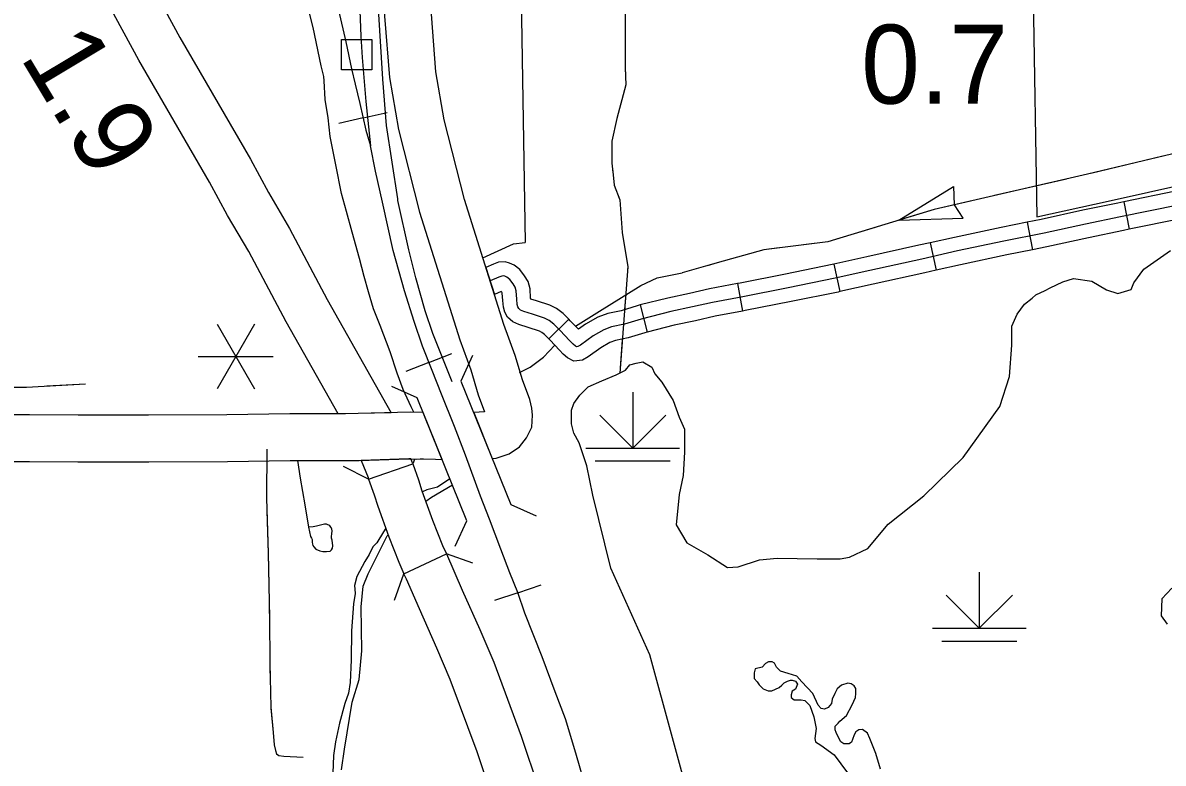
# Model space of a CAD drawing. Extents: x -117616 to 64730, y 54117 to 789866.
# Drawn here: x 63045.9 to 63167.8, y 54498.2 to 54577.4 of the extents above; entities that cross this region are included whole.
import ezdxf

# ---------------------------------------------------------------- set-up
doc = ezdxf.new("R2010")
doc.units = 0
for name, color, linetype in [('10', 7, 'Continuous'), ('32', 7, 'Continuous'), ('33', 7, 'Continuous'), ('34', 7, 'Continuous'), ('35', 7, 'Continuous'), ('37', 7, 'Continuous'), ('40', 7, 'Continuous'), ('43', 7, 'Continuous'), ('44', 7, 'Continuous'), ('47', 7, 'Continuous'), ('48', 7, 'Continuous'), ('6', 7, 'Continuous'), ('7', 7, 'Continuous')]:
    doc.layers.add(name, color=color, linetype=linetype)

msp = doc.modelspace()

# ---------------------------------------------------------------- linework, layer by layer
at = {"layer": '10'}
for p, q in [((63082.88, 54528.56), (63087.6, 54530.2)), ((63086.66, 54518.43), (63091.21, 54520.55)), ((63091.21, 54520.55), (63092.88, 54516.67)), ((63086.94, 54517.83), (63086.66, 54518.43)), ((63088.31, 54514.66), (63086.94, 54517.83)), ((63092.88, 54516.67), (63094.77, 54512.46)), ((63090.19, 54510.46), (63088.31, 54514.66)), ((63094.77, 54512.46), (63096.26, 54508.96)), ((63091.61, 54507.11), (63090.19, 54510.46)), ((63096.26, 54508.96), (63099.21, 54501.06)), ((63094.49, 54499.39), (63091.61, 54507.11)), ((63099.21, 54501.06), (63103.79, 54487.31)), ((63099, 54485.86), (63094.49, 54499.39))]:
    msp.add_line(p, q, dxfattribs=at)
for points in [[(63084.67, 54595.12), (63084.59, 54587.99), (63084.59, 54578.08), (63085.1, 54571.51), (63086.07, 54565.95), (63088.32, 54557.09), (63092.62, 54543.45), (63093.82, 54540.22), (63094.58, 54537.58), (63095.29, 54535.73), (63094.12, 54535.66)], [(63094.12, 54535.66), (63096.09, 54530.77), (63096.52, 54530.8), (63097.91, 54531.26), (63099, 54531.99), (63099.75, 54532.95), (63100.32, 54534.09), (63100.39, 54535.4), (63100.33, 54536.15), (63100.12, 54537.08), (63099.33, 54539.16), (63098.57, 54541.78), (63097.35, 54545.07), (63093.13, 54558.46), (63090.96, 54566.99), (63090.07, 54572.13), (63089.59, 54578.27), (63089.59, 54587.96), (63089.67, 54595.06)], [(63056.63, 54586.99), (63062.68, 54575.79), (63070.24, 54562.76), (63072.17, 54559.22), (63074.43, 54555.34), (63078.46, 54547.76), (63085.31, 54535.65), (63081.78, 54535.55), (63080.42, 54535.54), (63079.63, 54535.54)], [(63079.63, 54535.54), (63074.07, 54545.36), (63070.06, 54552.91), (63067.81, 54556.76), (63065.88, 54560.31), (63058.32, 54573.35), (63052.3, 54584.49)], [(63075.09, 54535.53), (63074.47, 54535.53), (63067.73, 54535.44), (63059.36, 54535.38), (63051.82, 54535.4), (63046.63, 54535.44), (63040.96, 54535.42), (63036.3, 54535.29), (63026.16, 54534.93), (63019.91, 54534.68), (63012.1, 54534.36), (63007.3, 54534.19), (63003.53, 54534.02), (62999.39, 54533.9), (62993.74, 54533.66), (62985.86, 54533.37), (62981.09, 54533.17), (62975.36, 54532.97), (62969.85, 54532.83), (62965.22, 54532.63), (62962.67, 54532.55), (62960.47, 54532.44), (62958.49, 54532.34), (62956.86, 54532.26)], [(63080.42, 54535.54), (63075.09, 54535.53)], [(63087.35, 54535.71), (63081.78, 54535.55), (63080.42, 54535.54)], [(63090.76, 54530.63), (63088.72, 54535.66), (63087.35, 54535.71)], [(62957.03, 54527.26), (62958.75, 54527.35), (62960.72, 54527.45), (62962.86, 54527.55), (62965.41, 54527.63), (62970.02, 54527.84), (62975.51, 54527.97), (62981.28, 54528.18), (62986.06, 54528.38), (62993.94, 54528.67), (62999.57, 54528.9), (63003.72, 54529.02), (63007.5, 54529.2), (63012.29, 54529.36), (63020.11, 54529.69), (63026.35, 54529.93), (63036.46, 54530.29), (63041.04, 54530.42), (63046.62, 54530.44), (63051.79, 54530.4), (63059.37, 54530.38), (63067.78, 54530.44), (63074.51, 54530.53), (63075.1, 54530.53)], [(63075.1, 54530.53), (63080.43, 54530.54)], [(63080.43, 54530.54), (63081.87, 54530.55), (63087.19, 54530.72)], [(63087.6, 54530.2), (63087.51, 54530.48), (63087.41, 54530.71), (63087.19, 54530.72), (63082.08, 54530.55)], [(63082.08, 54530.55), (63082.82, 54528.73), (63082.88, 54528.56)], [(63087.19, 54530.72), (63087.96, 54530.7), (63088.38, 54530.72), (63088.7, 54530.73), (63088.74, 54530.73), (63090.02, 54530.68)], [(63087.6, 54530.2), (63088.2, 54528.46), (63088.58, 54527.31), (63089.73, 54524.14), (63090.77, 54521.46), (63091.21, 54520.55)], [(63090.02, 54530.68), (63090.76, 54530.63)], [(63082.88, 54528.56), (63083.46, 54526.86), (63083.86, 54525.67), (63085.05, 54522.38), (63086.11, 54519.65), (63086.66, 54518.43)]]:
    msp.add_lwpolyline(points, dxfattribs=at)
at = {"layer": '32'}
for p, q in [((63163.62, 54558.21), (63164.22, 54555.27)), ((63153.29, 54556.03), (63153.88, 54553.09)), ((63142.93, 54553.83), (63143.58, 54550.9)), ((63095.43, 54551.18), (63096.33, 54548.3)), ((63132.62, 54551.53), (63133.28, 54548.6)), ((63122.32, 54549.47), (63122.87, 54546.52)), ((63111.92, 54547.18), (63112.65, 54544.27)), ((63104.3, 54545.65), (63102.16, 54543.55))]:
    msp.add_line(p, q, dxfattribs=at)
for points in [[(63174.22, 54559.99), (63174.01, 54560.03), (63173.5, 54560.05), (63172.99, 54560.03), (63172.34, 54559.95), (63171.71, 54559.83), (63170.9, 54559.65), (63169.15, 54559.34), (63163.62, 54558.21)], [(63163.62, 54558.21), (63162.98, 54558.08), (63159.24, 54557.3), (63154.81, 54556.33), (63153.29, 54556.03)], [(63169.43, 54557.86), (63163.28, 54556.61), (63159.55, 54555.83), (63155.12, 54554.86), (63150.82, 54554.01), (63145.84, 54552.95), (63142.04, 54552.09), (63136.49, 54550.86), (63132.78, 54550.03), (63127.76, 54549.01), (63122.88, 54548.04), (63119.65, 54547.44), (63117.51, 54546.96), (63115.21, 54546.46), (63112.02, 54545.66), (63110.25, 54545.11), (63108.87, 54544.82), (63108.02, 54544.51), (63106.88, 54543.86), (63105.53, 54542.89), (63105.25, 54542.72), (63105.1, 54542.71), (63105, 54542.76), (63104.75, 54542.99), (63104.38, 54543.37), (63103.37, 54544.46), (63102.7, 54545.14), (63102.2, 54545.52), (63101.7, 54545.76), (63100.39, 54546.19), (63099.47, 54546.48), (63099.14, 54546.63), (63098.94, 54546.81), (63098.84, 54546.99), (63098.77, 54547.23), (63098.72, 54547.78), (63098.65, 54548.68), (63098.55, 54549.09), (63098.34, 54549.43), (63097.97, 54549.91), (63097.67, 54550.14), (63097.44, 54550.24), (63097.32, 54550.28), (63097.12, 54550.26), (63096.82, 54550.14), (63095.88, 54549.74)], [(63173.89, 54556.99), (63173.8, 54557.02), (63173.68, 54557.04), (63173.49, 54557.05), (63173.24, 54557.04), (63172.79, 54556.98), (63172.31, 54556.89), (63171.49, 54556.71), (63169.71, 54556.39), (63164.22, 54555.27)], [(63153.29, 54556.03), (63150.52, 54555.48), (63145.52, 54554.41), (63142.93, 54553.83)], [(63164.22, 54555.27), (63163.59, 54555.14), (63159.86, 54554.36), (63155.42, 54553.39), (63153.88, 54553.09)], [(63142.93, 54553.83), (63141.71, 54553.56), (63136.16, 54552.32), (63132.62, 54551.53)], [(63153.88, 54553.09), (63151.12, 54552.54), (63146.16, 54551.48), (63143.58, 54550.9)], [(63104.3, 54545.65), (63103.7, 54546.27), (63102.98, 54546.81), (63102.26, 54547.15), (63100.84, 54547.62), (63100.22, 54547.81), (63100.21, 54547.9), (63100.14, 54548.91), (63099.95, 54549.69), (63099.56, 54550.29), (63099.05, 54550.97), (63098.44, 54551.45), (63097.94, 54551.66), (63097.47, 54551.79), (63096.78, 54551.74), (63096.25, 54551.53), (63095.43, 54551.18)], [(63132.62, 54551.53), (63132.46, 54551.49), (63127.47, 54550.48), (63122.6, 54549.52), (63122.32, 54549.47)], [(63143.58, 54550.9), (63142.37, 54550.63), (63136.82, 54549.4), (63133.28, 54548.6)], [(63122.32, 54549.47), (63119.34, 54548.91), (63117.19, 54548.42), (63114.87, 54547.92), (63111.92, 54547.18)], [(63102.16, 54543.55), (63101.7, 54544.02), (63101.42, 54544.23), (63101.15, 54544.36), (63099.93, 54544.76), (63098.94, 54545.07), (63098.3, 54545.36), (63097.74, 54545.87), (63097.44, 54546.42), (63097.29, 54546.95), (63097.22, 54547.65), (63097.17, 54548.44), (63097.15, 54548.49), (63097.11, 54548.56), (63097.07, 54548.62), (63096.33, 54548.3)], [(63096.47, 54548.36), (63096.47, 54548.36)], [(63133.28, 54548.6), (63133.09, 54548.56), (63128.05, 54547.54), (63123.16, 54546.57), (63122.87, 54546.52)], [(63111.92, 54547.18), (63111.61, 54547.1), (63109.87, 54546.56), (63108.45, 54546.27), (63107.38, 54545.87), (63106.07, 54545.12), (63105.31, 54544.58), (63104.45, 54545.49), (63104.3, 54545.65)], [(63122.87, 54546.52), (63119.95, 54545.97), (63117.84, 54545.49), (63115.56, 54545), (63112.65, 54544.27)], [(63112.65, 54544.27), (63112.42, 54544.21), (63110.62, 54543.65), (63109.28, 54543.38), (63108.66, 54543.15), (63107.7, 54542.59), (63106.35, 54541.63), (63105.74, 54541.27), (63104.83, 54541.17), (63104.14, 54541.51), (63103.7, 54541.92), (63103.29, 54542.34), (63102.28, 54543.42), (63102.16, 54543.55)]]:
    msp.add_lwpolyline(points, dxfattribs=at)
at = {"layer": '33'}
msp.add_lwpolyline([(63077.81, 54572.76), (63076.95, 54576.84), (63076.26, 54579.54), (63075.57, 54582.7), (63074.9, 54585.84), (63074.01, 54589.67), (63073.35, 54592.61), (63072.7, 54595.11), (63072.21, 54596.89), (63072.01, 54597.46), (63071.81, 54597.95), (63071.72, 54598.1)], dxfattribs=at)
at = {"layer": '34'}
for points in [[(63087.73, 54535.7), (63087.44, 54536.27), (63086.59, 54538.13), (63085.95, 54539.89), (63085.19, 54542.16), (63084.11, 54544.98), (63083.39, 54546.78), (63082.88, 54548.59), (63082.39, 54550.22), (63081.92, 54552.15), (63081.11, 54554.97), (63080.5, 54557.19), (63079.97, 54559.1), (63079.37, 54562.18), (63078.76, 54565.21), (63078.55, 54567.2), (63078.23, 54569.17), (63078.14, 54571.16), (63078.08, 54571.61), (63077.81, 54572.76)], [(63075.27, 54530.53), (63075.57, 54528.65), (63076.05, 54525.81), (63076.46, 54523.41)], [(63076.46, 54523.41), (63076.56, 54522.91), (63076.68, 54522.41), (63076.76, 54522.24), (63076.83, 54522.1), (63076.85, 54521.96), (63076.86, 54521.8), (63076.88, 54521.58), (63076.92, 54521.45), (63077.02, 54521.29), (63077.24, 54521.05), (63077.66, 54520.86), (63077.97, 54520.8), (63078.37, 54520.8), (63078.76, 54520.85), (63078.91, 54520.98), (63079.01, 54521.15), (63079.05, 54521.42), (63079, 54522.01), (63078.92, 54522.24), (63078.92, 54522.41), (63078.95, 54522.71), (63078.97, 54523.03), (63078.95, 54523.18), (63078.86, 54523.37), (63078.72, 54523.55), (63078.62, 54523.63), (63078.52, 54523.67), (63078.37, 54523.72), (63078.16, 54523.73), (63077.87, 54523.67), (63077.32, 54523.51), (63076.96, 54523.44), (63076.46, 54523.41)]]:
    msp.add_lwpolyline(points, dxfattribs=at)
at = {"layer": '35'}
for points in [[(63104.99, 54544.92), (63107.57, 54546.53), (63111.98, 54549.26), (63113.73, 54550.08), (63116.4, 54550.6)], [(63099.02, 54539.96), (63100.14, 54540.54), (63101.58, 54541.6), (63102.8, 54542.87)], [(63090.24, 54527.69), (63089.1, 54527.39), (63088.63, 54527.18)], [(63088.99, 54526.19), (63089.62, 54526.62), (63091.85, 54527.93)], [(63091.58, 54528.59), (63090.24, 54527.69)], [(63084.72, 54523.3), (63084.47, 54522.92), (63083.76, 54521.73), (63083.32, 54521.3), (63082.94, 54520.49), (63082.48, 54519.74), (63081.61, 54518.13), (63081.38, 54517.17), (63081.4, 54516.78), (63081.45, 54516.3), (63081.26, 54515.22), (63081.06, 54512.31), (63081.01, 54509.21), (63080.92, 54506.78), (63080.74, 54505.66), (63080.35, 54504.56), (63079.77, 54502.45), (63079.34, 54500.46), (63079.13, 54498.99), (63079.04, 54497.11)], [(63082.84, 54518.43), (63084.08, 54520.93), (63084.88, 54522.49), (63084.97, 54522.6)], [(63079.97, 54497.44), (63080.3, 54499.65), (63081.11, 54504.7), (63081.87, 54507.11), (63082.15, 54510.18), (63082.1, 54514.87), (63082.31, 54517.11), (63082.84, 54518.43)], [(63168.78, 54516.88), (63167.71, 54515.73), (63167.63, 54513.93), (63168.28, 54513.05)], [(63137.62, 54497.52), (63137.12, 54499.2), (63136.49, 54500.79), (63136.24, 54501.38), (63135.7, 54501.76), (63135.3, 54501.72), (63134.97, 54501.5), (63134.82, 54501.21), (63134.63, 54500.69), (63134.52, 54500.4), (63134.27, 54500.25), (63133.94, 54500.25), (63133.68, 54500.25), (63133.38, 54500.43), (63133.13, 54500.91), (63132.87, 54501.43), (63132.76, 54501.72), (63132.76, 54502.13), (63133.09, 54502.46), (63133.27, 54502.64), (63133.97, 54503.27), (63134.6, 54504.41), (63134.93, 54505.19), (63134.97, 54505.63), (63134.97, 54506.14), (63134.82, 54506.44), (63134.49, 54506.66), (63134.12, 54506.73), (63133.46, 54506.51), (63132.98, 54506.11), (63132.72, 54505.63), (63132.46, 54505), (63132.39, 54504.56), (63132.02, 54504.12), (63131.62, 54503.93), (63131.29, 54504.01), (63130.95, 54504.38), (63130.4, 54505.63), (63129.19, 54506.88), (63128.67, 54507.47), (63127.75, 54507.76), (63126.94, 54507.99), (63126.5, 54508.43), (63126.28, 54508.87), (63126.02, 54509.02), (63125.65, 54509.02), (63125.32, 54508.83), (63124.96, 54508.43), (63124.22, 54508.24), (63124.11, 54507.84), (63124.11, 54507.54), (63124.11, 54507.21), (63124.44, 54506.88), (63124.66, 54506.55), (63124.81, 54506.36), (63125.07, 54506.11), (63125.62, 54505.89), (63125.99, 54505.89), (63126.8, 54506.25), (63127.05, 54506.51), (63127.31, 54506.77), (63127.68, 54506.95), (63128.01, 54507.03), (63128.19, 54507.03), (63128.53, 54506.92), (63128.75, 54506.62), (63128.67, 54506.44), (63128.53, 54506.07), (63128.16, 54505.85), (63128.05, 54505.48), (63128.08, 54505.19), (63128.38, 54504.93), (63129.15, 54504.93), (63129.52, 54504.85), (63130.07, 54504.34), (63130.48, 54503.12)], [(63130.48, 54503.12), (63130.73, 54501.87), (63130.59, 54500.8), (63130.66, 54500.43), (63131.25, 54500.1), (63132.68, 54499.07), (63134.08, 54497.12)]]:
    msp.add_lwpolyline(points, dxfattribs=at)
at = {"layer": '37'}
for points in [[(63093.99, 54541.76), (63092.76, 54539.02)], [(63088.08, 54537.24), (63085.35, 54538.47)], [(63082.88, 54528.56), (63080.18, 54529.88)], [(63087.8, 54530.63), (63087.6, 54530.2)], [(63098.08, 54525.85), (63100.81, 54524.61)], [(63092.15, 54521.37), (63093.39, 54524.1)], [(63091.18, 54520.58), (63094, 54519.58)], [(63085.66, 54515.61), (63086.66, 54518.43)]]:
    msp.add_lwpolyline(points, dxfattribs=at)
at = {"layer": '40'}
for p, q in [((63082.29, 54567.18), (63084.86, 54567.76)), ((63082.29, 54567.18), (63079.71, 54566.6)), ((63089.33, 54541.02), (63086.87, 54540.07)), ((63089.33, 54541.02), (63091.79, 54541.98)), ((63092.76, 54539.02), (63098.08, 54525.85)), ((63098.85, 54516.4), (63101.35, 54517.24)), ((63098.85, 54516.4), (63096.34, 54515.56))]:
    msp.add_line(p, q, dxfattribs=at)
for points in [[(63070.77, 54618.7), (63071.46, 54616), (63072.4, 54611.53), (63073.22, 54608.04), (63074.22, 54603.33), (63075.12, 54599.36), (63075.67, 54596.47), (63076.72, 54591.57), (63077.85, 54586.72), (63078.84, 54582.33), (63079.65, 54578.7), (63080.43, 54575.33), (63081.05, 54572.42), (63081.45, 54570.81), (63081.94, 54568.73), (63082.59, 54565.88), (63083.07, 54564.21)], [(63075.12, 54599.36), (63075.67, 54596.47), (63076.72, 54591.57), (63077.85, 54586.72), (63078.84, 54582.33), (63079.65, 54578.7), (63080.43, 54575.33), (63081.05, 54572.42), (63081.45, 54570.81), (63081.94, 54568.73), (63082.59, 54565.88), (63083.07, 54564.21)], [(63082.84, 54597.41), (63082.63, 54595.15), (63082.37, 54591.4), (63081.85, 54585.98), (63081.8, 54584.31), (63081.9, 54579.57), (63082.06, 54575.92), (63082.21, 54573.63), (63082.58, 54568.93), (63083.07, 54564.21)], [(63087.74, 54545.41), (63086.71, 54548.69), (63085.52, 54553), (63084.36, 54558.17), (63083.63, 54561.49), (63083.07, 54564.21)], [(63092.08, 54534.18), (63090.69, 54537.65), (63089.66, 54540.17), (63088.65, 54542.78), (63087.74, 54545.41), (63086.71, 54548.69), (63085.52, 54553), (63084.36, 54558.17), (63083.63, 54561.49), (63083.07, 54564.21)], [(63106.35, 54494.66), (63105.05, 54499.25), (63103.95, 54502.9), (63102.84, 54505.81), (63101.43, 54509.54), (63099.58, 54514.21), (63098.84, 54516.43), (63097.98, 54518.53), (63097.01, 54521.07), (63095.8, 54524.25), (63094.83, 54526.72), (63093.23, 54531.11), (63092.08, 54534.18), (63090.69, 54537.65), (63089.66, 54540.17), (63088.65, 54542.78), (63087.74, 54545.41)], [(63093.39, 54524.1), (63088.08, 54537.24)], [(63106.35, 54494.66), (63105.05, 54499.25), (63103.95, 54502.9), (63102.84, 54505.81), (63101.43, 54509.54), (63099.58, 54514.21), (63098.84, 54516.43), (63097.98, 54518.53), (63097.01, 54521.07), (63095.8, 54524.25), (63094.83, 54526.72), (63093.23, 54531.11), (63092.08, 54534.18)]]:
    msp.add_lwpolyline(points, dxfattribs=at)
msp.add_lwpolyline([(63079.97, 54575.58), (63083.24, 54575.58), (63083.24, 54572.31), (63079.97, 54572.31)], close=True, dxfattribs=at)
at = {"layer": '43'}
for p, q in [((63139.59, 54556.24), (63145.42, 54559.86)), ((63145.42, 54559.86), (63145.51, 54557.89)), ((63146.45, 54556.46), (63145.52, 54557.87)), ((63139.59, 54556.24), (63146.45, 54556.46))]:
    msp.add_line(p, q, dxfattribs=at)
for points in [[(63110.67, 54579.58), (63110.33, 54578.56), (63110.33, 54575.19), (63110.33, 54572.53), (63110.35, 54571.71)], [(63110.33, 54578.56), (63110.33, 54575.19), (63110.33, 54572.53), (63110.37, 54570.72), (63109.41, 54567.13), (63108.89, 54564.71), (63108.89, 54562.34), (63109.02, 54561.1), (63109.15, 54559.98), (63109.74, 54558.41), (63110, 54554.93), (63110.59, 54551.26), (63110.33, 54547.52), (63109.73, 54539.87)], [(63207.19, 54577.49), (63207.38, 54574.68), (63206.93, 54572.57), (63206.19, 54571.14), (63205.5, 54570.37), (63204.77, 54569.96), (63203.88, 54569.6), (63202.49, 54569.03), (63201.27, 54568.74), (63198.79, 54568.46), (63191.27, 54568.36), (63186.06, 54568.04), (63173.98, 54564.57), (63159.77, 54561.17), (63143.35, 54557.38), (63131.99, 54553.94), (63125.15, 54553.07), (63120.16, 54551.68), (63116.4, 54550.6)], [(63109.95, 54569.13), (63109.41, 54567.13), (63108.89, 54564.71), (63108.89, 54562.34), (63108.99, 54561.34)], [(63167.8, 54563.09), (63160.1, 54561.25)], [(63157.52, 54560.65), (63149.81, 54558.87)], [(63109.6, 54558.79), (63109.74, 54558.41), (63110, 54554.93), (63110.59, 54551.26), (63110.57, 54550.96)], [(63147.23, 54558.28), (63143.35, 54557.38), (63139.59, 54556.24)], [(63137.06, 54555.47), (63133.27, 54554.33)], [(63133.27, 54554.33), (63131.99, 54553.94), (63129.39, 54553.61)], [(63126.77, 54553.27), (63125.15, 54553.07), (63120.16, 54551.68), (63119.1, 54551.37)], [(63116.56, 54550.64), (63116.4, 54550.6)], [(63110.39, 54548.32), (63110.33, 54547.52), (63110.26, 54546.68)], [(63110.01, 54543.46), (63109.77, 54540.43)], [(63041.37, 54538.38), (63046.3, 54538.38), (63052.6, 54538.75)], [(63048.48, 54538.51), (63052.6, 54538.75)], [(63071.99, 54531.75), (63071.96, 54526.51), (63072.15, 54520.61), (63072.27, 54513.7), (63072.31, 54508.85), (63072.42, 54504.16), (63072.68, 54501.43), (63072.8, 54500.12), (63072.91, 54499.51), (63073.05, 54499.16), (63073.28, 54498.97), (63073.8, 54498.93), (63075.88, 54498.8)], [(63071.99, 54530.5), (63071.97, 54527.79)], [(63072, 54525.15), (63072.15, 54520.61), (63072.21, 54517.23)], [(63072.25, 54514.59), (63072.27, 54513.7), (63072.31, 54508.85), (63072.36, 54506.67)], [(63072.44, 54504.04), (63072.68, 54501.43), (63072.8, 54500.12), (63072.91, 54499.51), (63073.05, 54499.16), (63073.28, 54498.97), (63073.8, 54498.93), (63075.88, 54498.8)]]:
    msp.add_lwpolyline(points, dxfattribs=at)
at = {"layer": '44'}
for p, q in [((63111.12, 54537.85), (63111.12, 54531.85)), ((63111.12, 54531.85), (63107.59, 54535.39)), ((63111.12, 54531.85), (63114.66, 54535.39)), ((63106.12, 54531.85), (63116.12, 54531.85)), ((63107.12, 54530.49), (63115.12, 54530.49)), ((63148.18, 54518.6), (63148.18, 54512.6)), ((63148.18, 54512.6), (63144.65, 54516.13)), ((63148.18, 54512.6), (63151.72, 54516.13)), ((63143.18, 54512.6), (63153.18, 54512.6)), ((63144.18, 54511.23), (63152.18, 54511.23))]:
    msp.add_line(p, q, dxfattribs=at)
at = {"layer": '47'}
for points in [[(63124.69, 54519.91), (63126.56, 54520.09), (63130.83, 54520.03), (63133.29, 54520.03), (63134.29, 54520.21), (63136.27, 54521.14), (63138.44, 54523.72), (63142.24, 54526.76), (63146.45, 54530.86), (63150.37, 54536.31), (63151.42, 54539.53), (63151.66, 54542.86), (63151.66, 54544.91), (63152.24, 54546.2), (63153, 54547.25), (63153.82, 54547.9), (63154.23, 54548.25), (63155.23, 54548.72), (63155.75, 54549.01), (63157.1, 54549.65), (63158.27, 54550), (63160.2, 54549.71), (63161.78, 54548.78), (63163.01, 54548.42), (63164.41, 54548.83), (63164.7, 54549.54), (63165.76, 54551), (63168.62, 54552.99)], [(63117.8, 54491.99), (63112.94, 54509.77), (63108.8, 54519.02), (63106.85, 54526.82), (63106.21, 54529.98), (63105.39, 54532.42), (63104.83, 54533.47), (63104.58, 54534.45), (63104.58, 54535.1), (63104.58, 54535.91), (63104.83, 54536.64), (63105.48, 54537.53), (63106.37, 54538.42), (63107.83, 54539.07), (63109.37, 54539.72), (63110.34, 54540.21), (63110.83, 54540.78), (63111.48, 54540.94), (63112.21, 54541.1), (63113.18, 54540.53), (63113.5, 54539.8), (63114.23, 54538.91), (63115.45, 54536.96), (63116.1, 54535.18), (63116.67, 54533.88), (63116.67, 54532.98), (63116.67, 54532.5), (63116.67, 54531.44), (63116.51, 54528.93), (63116.1, 54526.9), (63115.78, 54523.65), (63116.91, 54521.73), (63119.14, 54520.44), (63121.24, 54519.09), (63122.41, 54519.15), (63124.69, 54519.91)]]:
    msp.add_lwpolyline(points, dxfattribs=at)
at = {"layer": '48'}
for p, q in [((63070.67, 54545.12), (63066.67, 54538.19)), ((63066.67, 54545.12), (63070.67, 54538.19)), ((63064.67, 54541.66), (63072.67, 54541.66))]:
    msp.add_line(p, q, dxfattribs=at)
at = {"layer": '6'}
for points in [[(63097.25, 54623.65), (63098.12, 54623.69), (63098.76, 54606.24), (63099.64, 54553.85)], [(63095.09, 54552.23), (63098.36, 54553.71), (63099.64, 54553.85)]]:
    msp.add_lwpolyline(points, dxfattribs=at)
at = {"layer": '7'}
for p, q in [((63153.79, 54589.54), (63154.33, 54556.59)), ((63084.4, 54571.34), (63083.93, 54578.87)), ((63084.8, 54566.36), (63084.4, 54571.34)), ((63086, 54558.53), (63084.8, 54566.36)), ((63161.97, 54558.27), (63192.99, 54565.27)), ((63086.02, 54558.36), (63086, 54558.53)), ((63087.19, 54553.09), (63086.02, 54558.36)), ((63154.33, 54556.59), (63161.97, 54558.27)), ((63087.93, 54550.07), (63087.19, 54553.09)), ((63088.92, 54546.54), (63087.93, 54550.07)), ((63089.76, 54544.12), (63088.92, 54546.54)), ((63091.83, 54538.97), (63089.76, 54544.12))]:
    msp.add_line(p, q, dxfattribs=at)

# ---------------------------------------------------------------- texts
at = {"layer": '48'}
msp.add_text('1.9', height=8.448, rotation=300.9416, dxfattribs=at).set_placement((63045.53, 54573.74))
msp.add_text('0.7', height=8.448, dxfattribs=at).set_placement((63135.55, 54568.71))

doc.saveas('drawing.dxf')
